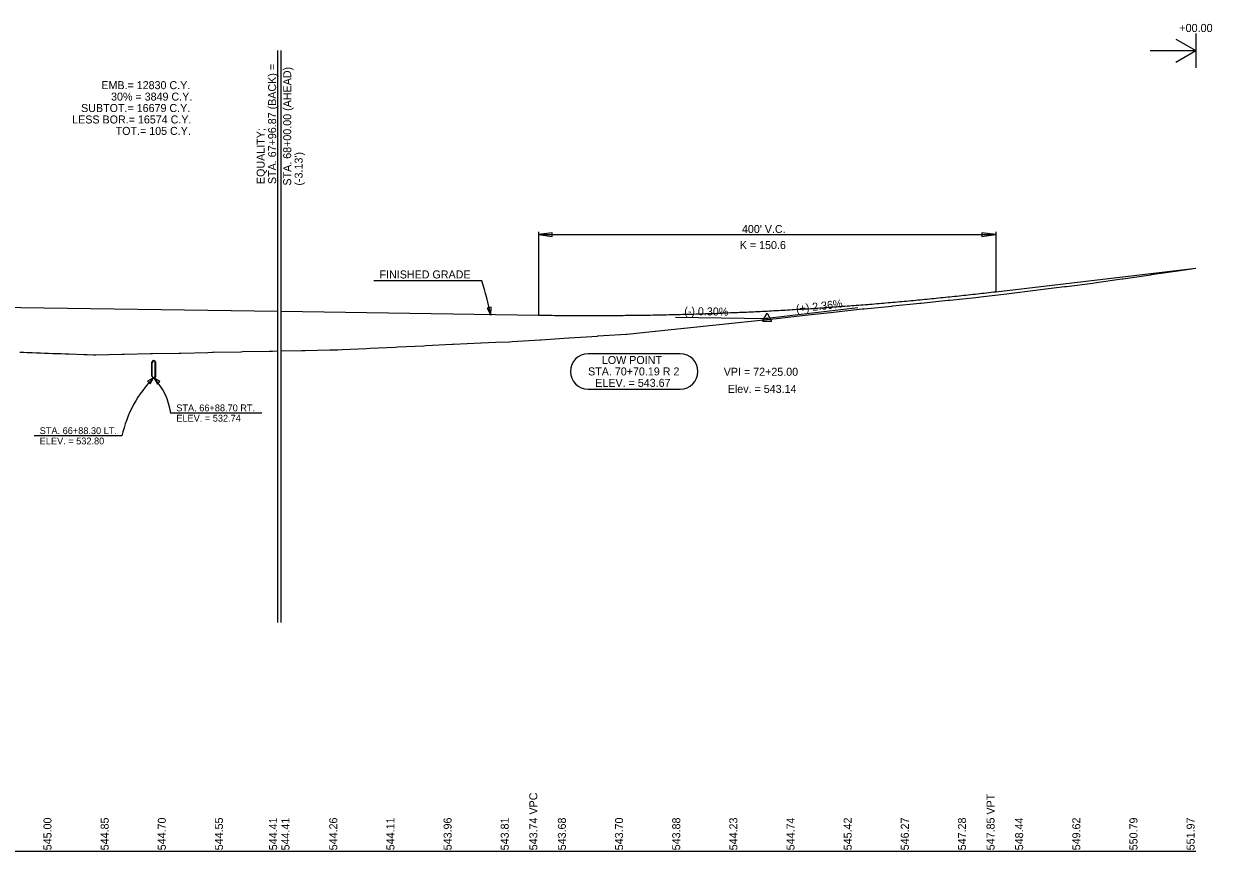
# Model space of a CAD drawing. Extents: x 49922 to 52614, y 49991 to 60509.
# Drawn here: x 51575 to 52614, y 52500 to 53223 of the extents above; entities that cross this region are included whole.
import ezdxf

# ---------------------------------------------------------------- set-up
doc = ezdxf.new("R2010")
doc.units = 0
for name, color, linetype in [('RD_DDB_GradeTX', 7, 'Continuous'), ('RD_DDB_Profile_EX', 7, 'Continuous'), ('RD_DDB_Profile_Lbl', 7, 'Continuous'), ('RD_DDB_Profile_PR', 7, 'Continuous'), ('RD_DDB_StripGrade', 7, 'Continuous'), ('RD_DDB_VCLbl', 7, 'Continuous'), ('RD_GPK_Profile_Cell', 7, 'Continuous'), ('RD_Sketch2', 7, 'Continuous'), ('RD_TX_Profile', 7, 'Continuous')]:
    doc.layers.add(name, color=color, linetype=linetype)

msp = doc.modelspace()

# ---------------------------------------------------------------- linework, layer by layer
at = {"layer": 'RD_DDB_GradeTX'}
for p, q in [((52304.5, 52975), (52225, 52965.7)), ((52145, 52966.9), (52225, 52965.7)), ((52221, 52963.4), (52225, 52970.3)), ((52221, 52963.4), (52229, 52963.4)), ((52225, 52970.3), (52229, 52963.4))]:
    msp.add_line(p, q, dxfattribs=at)
msp.add_circle((52225, 52965.7), 0.529, dxfattribs=at)
at = {"layer": 'RD_DDB_Profile_EX'}
for points in [[(51800, 52937.4), (51817.6, 52937.8), (51820.9, 52937.8), (51842.6, 52938.3), (51843.6, 52938.3), (51849.5, 52938.4), (51853.4, 52938.6), (51874.5, 52939.6), (51877.8, 52939.8), (51899.6, 52940.8), (51902.1, 52940.9), (51924.6, 52942), (51926.4, 52942.1), (51949.6, 52943.2), (51950.7, 52943.2), (51974.7, 52944.4), (51975, 52944.4), (51987.6, 52945), (51999.4, 52945.5), (51999.7, 52945.5), (52002, 52945.6), (52026.6, 52947.2), (52027, 52947.2), (52051.6, 52948.8), (52052, 52948.8), (52076.6, 52950.4), (52077, 52950.5), (52101.6, 52952), (52102, 52952.1), (52102.5, 52952.1), (52127.1, 52954.7), (52127.5, 52954.7), (52152.2, 52957.3), (52152.5, 52957.3), (52177.5, 52959.9), (52202.5, 52962.5), (52208.2, 52963.1), (52233.2, 52965.9), (52258.2, 52968.6), (52283.2, 52971.4), (52308.1, 52974.1), (52309.8, 52974.3), (52334.1, 52976.7), (52334.9, 52976.8), (52358.6, 52979.2), (52359.9, 52979.3), (52383, 52981.7), (52384.9, 52981.9), (52407.5, 52984.1), (52410, 52984.4), (52411.8, 52984.6), (52434.6, 52987.4), (52436.8, 52987.7), (52459.9, 52990.5), (52461.8, 52990.8), (52485.2, 52993.7), (52486.8, 52993.9), (52510, 52996.7), (52511.2, 52996.9), (52535.3, 53000.4), (52536.2, 53000.5), (52560.6, 53004.1), (52561.2, 53004.2), (52586.3, 53007.8), (52600, 53009.9)], [(51571.3, 52936.3), (51574.9, 52936.2), (51577.6, 52936.1), (51578.5, 52936.1), (51579.7, 52936.1)], [(51579.7, 52936.1), (51582.1, 52936), (51585.7, 52935.8), (51589.3, 52935.7), (51592.9, 52935.6), (51596.5, 52935.5), (51600.1, 52935.3), (51603, 52935.2), (51603.8, 52935.2), (51604.7, 52935.2), (51607.4, 52935.1), (51611, 52934.9), (51614.6, 52934.8), (51627.6, 52934.3), (51629.7, 52934.2), (51630.1, 52934.2), (51635.5, 52934), (51637.8, 52934.1), (51660.5, 52934.5), (51662.6, 52934.6), (51685.5, 52935.1), (51687.4, 52935.1), (51710.5, 52935.6), (51712.1, 52935.6), (51735.8, 52936.1), (51739.6, 52936.2), (51740.8, 52936.2), (51764.5, 52936.7), (51766.5, 52936.8), (51789.5, 52937.2), (51792.2, 52937.3), (51796.9, 52937.4)]]:
    msp.add_lwpolyline(points, dxfattribs=at)
at = {"layer": 'RD_DDB_Profile_PR'}
for p, q in [((52425, 52989.2), (52600, 53009.9)), ((50750, 52987.8), (51796.9, 52972.1)), ((51800, 52972.1), (52025, 52968.7))]:
    msp.add_line(p, q, dxfattribs=at)
msp.add_spline([(52025, 52968.7), (52033, 52968.6), (52041, 52968.5), (52049, 52968.4), (52057, 52968.4), (52065, 52968.4), (52073, 52968.4), (52081, 52968.4), (52089, 52968.4), (52097, 52968.5), (52105, 52968.6), (52113, 52968.7), (52121, 52968.8), (52129, 52968.9), (52137, 52969.1), (52145, 52969.3), (52153, 52969.5), (52161, 52969.7), (52169, 52970), (52177, 52970.2), (52185, 52970.5), (52193, 52970.9), (52201, 52971.2), (52209, 52971.5), (52217, 52971.9), (52225, 52972.3), (52233, 52972.8), (52241, 52973.2), (52249, 52973.7), (52257, 52974.1), (52265, 52974.6), (52273, 52975.2), (52281, 52975.7), (52289, 52976.3), (52297, 52976.9), (52305, 52977.5), (52313, 52978.1), (52321, 52978.8), (52329, 52979.5), (52337, 52980.2), (52345, 52980.9), (52353, 52981.6), (52361, 52982.4), (52369, 52983.2), (52377, 52984), (52385, 52984.8), (52393, 52985.6), (52401, 52986.5), (52409, 52987.4), (52417, 52988.3), (52425, 52989.2)], degree=3, dxfattribs=at)
at = {"layer": 'RD_DDB_VCLbl'}
for p, q in [((51796.9, 52700), (51796.9, 53200)), ((51800, 52700), (51800, 53200)), ((52025, 53041.7), (52025, 52968.7)), ((52037, 53040.6), (52025, 53039.1)), ((52025, 53039.2), (52425, 53039.2)), ((52025, 53039.1), (52037, 53037.6)), ((52037, 53037.6), (52037, 53040.6)), ((52425, 53039.1), (52413, 53040.6)), ((52413, 53040.6), (52413, 53037.6)), ((52413, 53037.6), (52425, 53039.1)), ((52425, 53041.7), (52425, 52989.2))]:
    msp.add_line(p, q, dxfattribs=at)
at = {"layer": 'RD_GPK_Profile_Cell'}
msp.add_line((50000, 52500), (52600, 52500), dxfattribs=at)
at = {"layer": 'RD_Sketch2'}
for p, q in [((51686.8, 52915.5), (51686.8, 52927.5)), ((51687.2, 52915.2), (51687.2, 52927.2)), ((51689.8, 52915.5), (51689.8, 52927.5)), ((51690.2, 52915.2), (51690.2, 52927.2))]:
    msp.add_line(p, q, dxfattribs=at)
for centre, start, end in [((51688.3, 52927.5), 360, 180), ((51688.7, 52927.2), 360, 180), ((51688.3, 52915.5), 180, 0), ((51688.7, 52915.2), 180, 0)]:
    msp.add_arc(centre, 1.5, start, end, dxfattribs=at)
at = {"layer": 'RD_TX_Profile'}
for p, q in [((52600, 53215), (52600, 53185)), ((52560, 53200), (52600, 53200)), ((52582.7, 53210), (52600, 53200)), ((52582.7, 53190), (52600, 53200)), ((51975.6, 52998.8), (51881, 52998.8)), ((52149, 52935), (52068.5, 52935)), ((52068.5, 52904), (52149, 52904)), ((51783, 52883.1), (51703.2, 52883.1)), ((51660.5, 52863.2), (51583.7, 52863.2))]:
    msp.add_line(p, q, dxfattribs=at)
for points in [[(51980.1, 52974.9), (51983.2, 52968.6), (51983.6, 52975.6)], [(51685.3, 52908.8), (51688.3, 52914), (51683.1, 52911)], [(51693.8, 52910.6), (51688.7, 52913.7), (51691.6, 52908.4)]]:
    msp.add_lwpolyline(points, close=True, dxfattribs=at)
for centre, radius, start, end in [((51680.1, 52908.1), 309, 11.2888, 17.0526), ((52068.5, 52919.5), 15.5, 90, 270), ((52149, 52919.5), 15.5, 270, 90), ((51762.3, 52840.6), 104.2, 135.2071, 167.4766), ((51649.2, 52876.2), 54.5, 7.246, 43.5061)]:
    msp.add_arc(centre, radius, start, end, dxfattribs=at)

# ---------------------------------------------------------------- texts
at = {"layer": 'RD_DDB_GradeTX'}
for s, rotation, p in [('(+) 2.36%', 6.7175, (52250.7, 52970.7)), ('(-) 0.30%', 359.1406, (52152.5, 52968.8))]:
    msp.add_text(s, height=7, rotation=rotation, dxfattribs=at).set_placement(p)
at = {"layer": 'RD_DDB_Profile_Lbl'}
for s, p in [('VPI = 72+25.00', (52187.1, 52915.7)), ('Elev. = 543.14', (52190.6, 52900.7))]:
    msp.add_text(s, height=7, dxfattribs=at).set_placement(p)
at = {"layer": 'RD_DDB_StripGrade'}
for s, p in [('543.74 VPC', (52024, 52500.8)), ('547.85 VPT', (52424, 52500.8)), ('545.00', (51599, 52500.8)), ('544.85', (51649, 52500.8)), ('544.70', (51699, 52500.8)), ('544.55', (51749, 52500.8)), ('544.41', (51796.4, 52500.8)), ('544.41', (51807.2, 52500.7)), ('544.26', (51849, 52500.8)), ('544.11', (51899, 52500.8)), ('543.96', (51949, 52500.8)), ('543.81', (51999, 52500.8)), ('543.68', (52049, 52500.8)), ('543.70', (52099, 52500.8)), ('543.88', (52149, 52500.8)), ('544.23', (52199, 52500.8)), ('544.74', (52249, 52500.8)), ('545.42', (52299, 52500.8)), ('546.27', (52349, 52500.8)), ('547.28', (52399, 52500.8)), ('548.44', (52449, 52500.8)), ('549.62', (52499, 52500.8)), ('550.79', (52549, 52500.8)), ('551.97', (52599, 52500.8))]:
    msp.add_text(s, height=7, rotation=90, dxfattribs=at).set_placement(p)
at = {"layer": 'RD_DDB_VCLbl'}
for s, p in [("400' V.C.", (52203, 53040.5)), ('K = 150.6', (52201.1, 53026.5))]:
    msp.add_text(s, height=7, dxfattribs=at).set_placement(p)
at = {"layer": 'RD_TX_Profile'}
for s, height, p in [('+00.00', 7.06, (52585.6, 53216.3)), ('EMB.= 12830 C.Y.', 7, (51642.6, 53166.3)), ('30% = 3849 C.Y.', 7, (51651.1, 53156.3)), ('SUBTOT.= 16679 C.Y.', 7, (51624.9, 53146.3)), ('LESS BOR.= 16574 C.Y.', 7, (51617.1, 53136.3)), ('TOT.= 105 C.Y.', 7, (51655.1, 53126.3)), ('FINISHED GRADE', 7, (51886, 53000.8)), ('STA. 66+88.70 RT.', 6, (51708.2, 52884.6)), ('ELEV. = 532.74', 6, (51708.2, 52875.6)), ('STA. 66+88.30 LT.', 6, (51588.7, 52864.7)), ('ELEV. = 532.80', 6, (51588.7, 52855.7))]:
    msp.add_text(s, height=height, dxfattribs=at).set_placement(p)
for s, rotation, p in [('STA. 67+96.87 (BACK) =', 90, (51795.5, 53083.3)), ('STA. 68+00.00 (AHEAD)', 90, (51808.7, 53082)), ('EQUALITY;', 90, (51785.5, 53083.3)), ("(-3.13')", 90, (51818.7, 53082)), ('LOW POINT', 360, (52080.5, 52926)), ('STA. 70+70.19 R 2', 360, (52068.4, 52916)), ('ELEV. = 543.67', 360, (52074.7, 52906))]:
    msp.add_text(s, height=7, rotation=rotation, dxfattribs=at).set_placement(p)

doc.saveas('drawing.dxf')
